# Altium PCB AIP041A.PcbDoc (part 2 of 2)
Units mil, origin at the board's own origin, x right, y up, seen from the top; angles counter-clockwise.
Board outline 2650 x 1600 mil, 2 copper layers (Top Layer, Bottom Layer), stack 62 mil thick; 99 components, 51 nets, 275 pads, 83 vias.
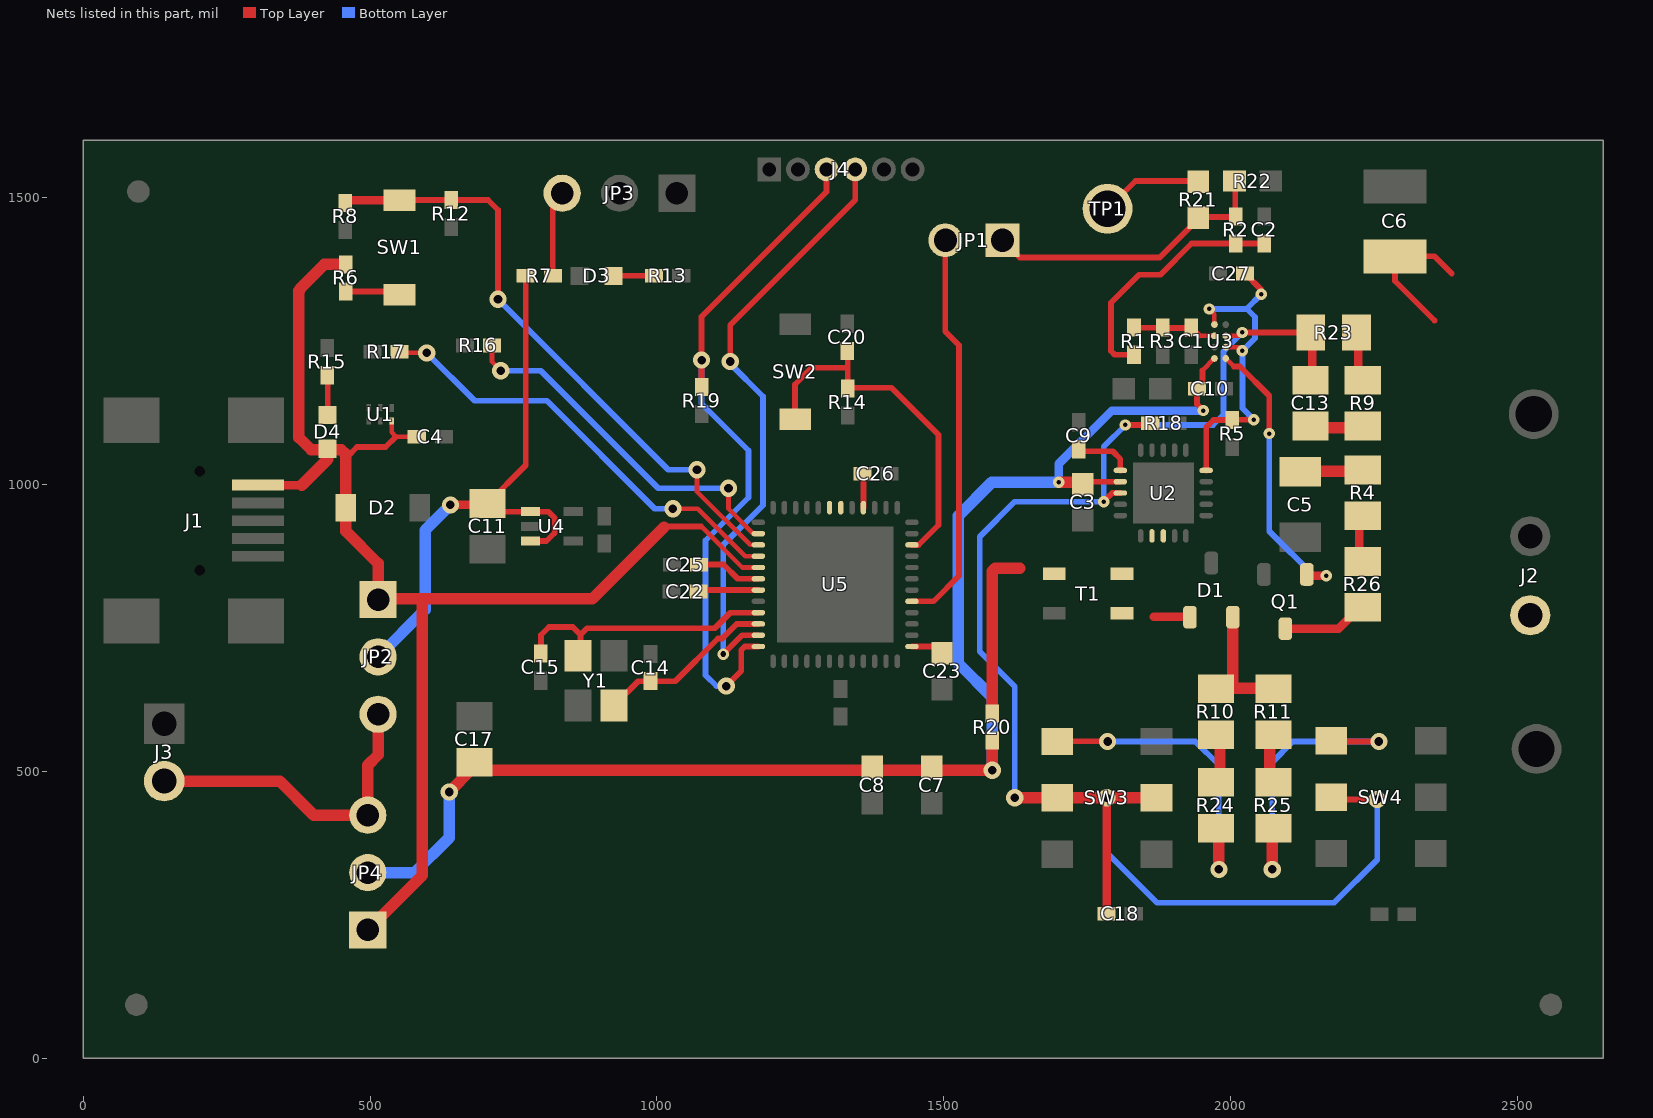
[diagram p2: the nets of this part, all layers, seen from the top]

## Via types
v1: diameter 30, hole 15, Top Layer to Bottom Layer, tented both sides, 48 vias
v2: diameter 19.68, hole 7.87, Top Layer to Bottom Layer, tented both sides, 17 vias
v3: diameter 19.68, hole 7.87, Top Layer to Bottom Layer, tented bottom, 17 vias
v4: diameter 20, hole 10, Top Layer to Bottom Layer, tented both sides, 1 vias

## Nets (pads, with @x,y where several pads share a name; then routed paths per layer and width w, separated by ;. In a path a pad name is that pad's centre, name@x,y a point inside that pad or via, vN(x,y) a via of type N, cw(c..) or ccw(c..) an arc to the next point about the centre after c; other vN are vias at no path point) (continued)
HV: C5.1 C6.1 C13.1 D1.2 J2.1 R4.2 R9.2 R10.2 R11.2 | length 653.9
  Top Layer w10: 2356,1286 2287,1355 C6.1@2287,1397.98 2356.02,1397.98 2386,1368
  Top Layer w20: R10.2@1968,645 R11.2@2056,645 ; R10.2@2004.4,647.31 D1.2@2004.4,771.76 ; C5.1@2113,1023.09 R4.2@2223.09,1023.09 ; C13.1@2140.57,1099 R9.2@2220,1099
NetC1_2: C1.2 R1.2 R3.2 U3.C2 | length 145.5
  Top Layer w8: 1945.9,1259.34 U3.C2@1972.28,1259.34
  Top Layer w10: R1.2@1832,1273.62 R3.2@1881.62,1273.62 ; R3.2@1882.12,1273.12 1932.12,1273.12 1945.9,1259.34
NetC2_1: C2.1 R1.1 R2.2 | length 437.1
  Top Layer w10: R1.1@1832,1226.38 1798.62,1226.38 1792,1233 1792,1317 1841,1366 1878,1366 1932.39,1420.39 R2.2@2009.49,1420.39 C2.1@2059.49,1420.39
NetC9_1: C9.1 U2.1 | length 97.9
  Top Layer w10: C9.1@1736,1058 1795,1058 1808.28,1044.72 U2.1@1808.28,1024.64
NetC14_2: C14.2 U5.46 Y1.1 | length 310.8
  Top Layer w10: Y1.1@925.31,614.7 967.51,656.9 988,656.9 1032,656.9 1106.62,731.52 1114,731.52 1139.46,756.98 U5.46@1177.13,756.98
NetC15_2: C15.2 U5.45 Y1.3 | length 462.4
  Top Layer w10: C15.2@798,705.15 798,737.52 812,751.52 853.49,751.52 867,738.01 ; Y1.3@867,714.52 867,738.01 ; U5.45@1177.13,776.67 1128,776.67 1100.86,749.52 878.51,749.52 867,738.01
NetC22_1: C22.1 U5.43 | length 106.1
  Top Layer w10: C22.1@1071.03,816.04 U5.43@1177.13,816.04
NetC23_1: C23.1 U5.13 | length 40.9
  Top Layer w10: U5.13@1444.85,717.61 C23.1@1485.75,717.61
NetC25_1: C25.1 U5.42 | length 113.8
  Top Layer w10: C25.1@1073.62,860.52 1116.48,860.52 1141.28,835.72 U5.42@1177.13,835.72
NetC26_2: C26.2 U5.28 | length 50.1
  Top Layer w10: U5.28@1360.2,959.74 C26.2@1360.2,1009.86
NetD1_1: D1.1 T1.2 | length 62.7
  Top Layer w15: 1866.88,769.76 D1.1@1929.6,769.76
NetD3_2: D3.2 R13.2 | length 66.9
  Top Layer w10: D3.2@924.53,1364 R13.2@991.38,1364
NetD4_2: D4.2 R15.2 | length 68.1
  Top Layer w10: D4.2@426,1121.56 R15.2@426,1189.62
NetJP1_1: JP1.1 R2.1 R21.1 R22.2 | length 508.2
  Top Layer w10: JP1.1@1603,1426 1632.99,1396 1877,1396 R21.1@1944,1463 ; R21.1@1944,1466.5 2008.36,1466.5 R22.2@2008.36,1529.14
NetJP3_3: JP3.3 R7.1 | length 150.8
  Top Layer w10: R7.1@818.62,1364 818.62,1491.62 JP3.3@835,1508
NetQ1_3: Q1.3 R26.1 | length 145.4
  Top Layer w15: Q1.3@2096,748.76 2188.76,748.76 R26.1@2226,786
NetR4_1: R4.1 R26.2 | length 78
  Top Layer w15: R26.2@2225,867 R4.1@2225,945
NetR6_1: R6.1 SW1.2 | length 87.9
  Top Layer w10: R6.1@457.37,1336.75 SW1.2@545.31,1336.75
NetR9_1: R9.1 R23.2 | length 82
  Top Layer w15: R9.1@2223,1183 R23.2@2223,1265
NetR10_1: R10.1 R24.2 | length 82
  Top Layer w20: R24.2@1982,481 R10.1@1982,563
NetR11_1: R11.1 R25.2 | length 79
  Top Layer w20: R25.2@2069,485 R11.1@2069,564
NetR16_1: R16.1 U5.38 | length 638.1
  Top Layer w8: R16.1@712.62,1242.52 712.62,1213.9 v1(728,1198.52) ; v1(1125,993.52) 1125,957.76 1168.3,914.46 U5.38@1177.13,914.46
  Bottom Layer w10: v1(728,1198.52) 797.48,1198.52 1002.48,993.52 v1(1125,993.52)
NetR17_1: R17.1 U5.40 | length 770.3
  Top Layer w8: R17.1@553.62,1229.52 v1(599,1229.52) ; v1(1028,958) 1071.52,958 1154.43,875.09 U5.40@1177.13,875.09
  Bottom Layer w10: v1(599,1229.52) 682.52,1146 808.52,1146 996.52,958 v1(1028,958)
NetR20_1: R20.1 T1.4 | length 298.4
  Top Layer w20: R20.1@1585,600.62 1585,849 1590,854 1633,854
NetR21_2: R21.2 TP1.1 | length 178.1
  Top Layer w10: TP1.1@1786,1481 1834.5,1529.5 R21.2@1944,1529.5
NetT1_1: T1.1 U2.7 U2.8
PUR: R8.1 R12.2 SW1.1 U5.39 | length 1083.1
  Top Layer w8: v1(1070,1026) 1070,987.52 1162.75,894.78 U5.39@1177.13,894.78
  Top Layer w10: SW1.1@551.37,1496.05 R12.2@641.52,1496.13 705.87,1496.13 723,1479 v1(723,1323)
  Top Layer w15: R8.1@457,1496.05 SW1.1@551.37,1496.05
  Bottom Layer w10: v1(723,1323) 1020,1026 v1(1070,1026)
PWM+_MSP: JP1.2 U5.17 | length 695.6
  Top Layer w10: U5.17@1444.85,796.35 1482.35,796.35 1527,841 1527,1243 1503,1267 JP1.2@1503,1426
REXT: C27.1 R5.1 U2.15 U3.B1 U3.D2 | length 592.2
  Top Layer w8: v2(1963.03,1306.18) 1972.28,1296.93 U3.D2@1972.28,1279.03 ; U3.B1@1991.96,1239.66 2014.55,1239.66 v2(2021.03,1233.18)
  Top Layer w10: U2.15@1957.89,1024.64 1957.89,1099.89 1970.62,1112.62 R5.1@2003,1112.62 ; R5.1@2003.38,1113 v2(2041,1113) ; C27.1@2025.62,1368 2054,1339.62 v2(2054,1332)
  Bottom Layer w10: v2(1963.03,1306.18) 2028.82,1306.18 ; v2(2041,1113) 2021.03,1132.97 v2(2021.03,1233.18) 2043,1255.15 2043,1292 2028.82,1306.18 ; v2(2054,1332) 2028.82,1306.82 2028.82,1306.18
RNET1: R24.1 SW3.1 | length 550.7
  Top Layer w10: SW3.1@1697.97,552.31 v1@1785.69,552.31
  Top Layer w20: v1(1980,329) R24.1@1980,399
  Bottom Layer w10: v1(1786,552) 1939,552 1980,511 v1(1980,329)
RNET2: R25.1 SW4.1 | length 541.6
  Top Layer w10: SW4.1@2177.28,552 v1(2259,552)
  Top Layer w20: v1(2073,329) R25.1@2073,401
  Bottom Layer w10: v1(2073,329) 2073,516 2109,552 v1(2259,552)
SBWTCK: J4.4 U5.47 | length 1060.5
  Top Layer w10: v4(1116,704.52) 1148.77,737.3 U5.47@1177.13,737.3 ; v1(1128,1214.52) 1128,1278 1346,1496 J4.4@1346,1551.49
  Bottom Layer w10: v4(1116,704.52) 1116,895 1185,964 1185,1153.81 v1@1128,1210.82
SBWTDIO: J4.3 R19.1 U5.48 | length 1234.2
  Top Layer w10: R19.1@1078,1170.15 v1(1078,1217) 1078,1292.52 1296,1510.52 J4.3@1296,1549.52 ; v1(1121,648.57) 1147.29,674.87 1147.29,711.52 1153.38,717.61 U5.48@1177.13,717.61
  Bottom Layer w10: v1(1078,1217) 1078,1141.52 1160,1059.52 1160,977.52 1085,902.52 1085,667.52 1103.95,648.57 v1(1121,648.57)
SCL: U5.31
SDA: U5.30
TRIG: C20.1 R14.1 SW2.2 U5.22 | length 640.1
  Top Layer w10: SW2.2@1241.05,1114.17 1241.05,1174.57 1270,1203.52 1333.05,1203.52 ; R14.1@1333.05,1167.47 C20.1@1333.05,1233.22 ; R14.1@1333.05,1169 1409,1169 1491,1087 1491,929.52 1456.25,894.78 U5.22@1444.85,894.78
VBUS: C4.1 D2.1 D4.1 J1.1 JP2.1 JP4.1 R6.2 U1.6 U5.41 | length 2416.7
  Top Layer w8: U1.6@537.48,1110.92 537.48,1091.04 545,1083.52 C4.1@581.38,1083.52 ; 1077.52,927 1149.12,855.41 U5.41@1177.13,855.41
  Top Layer w10: D4.1@426,1061 D4.1@426,1062.5 ; 461.03,1049.49 477.06,1065.52 527,1065.52 545,1083.52 ; 1011,927 1077.52,927
  Top Layer w15: J1.1@304.5,999 381,999
  Top Layer w20: 381,999 426,1044 D4.1@426,1061 ; R6.2@457.37,1384 420.48,1384 377,1340.52 377,1339 376,1338 376,1082 397,1061 D4.1@426,1061 ; D2.1@457.53,956.52 D2.1@457.53,959.52 ; JP4.1@496,223.52 591,318.52 591,800.52 ; JP2.1@514,799.52 514,862.52 457.53,918.99 D2.1@457.53,959.52 ; JP2.1@514,800.52 887.52,800.52 1012.5,925.5 ; D4.1@426,1061 449.53,1061 457.53,1052.99 D2.1@457.53,959.52
VDIV: C13.2 C18.1 R18.2 R23.1 SW3.2 SW3.5 SW4.2 U2.3 U3.C1 | length 2777.6
  Top Layer w8: U3.C1@1991.96,1259.34 2015.19,1259.34 v2(2021.03,1265.18)
  Top Layer w10: v2(1779.08,970.27) 1794.08,985.27 U2.3@1808.28,985.27 ; v2(1817,1104) R18.2@1857.38,1104 ; v2(2021.03,1265.18) R23.1@2143,1265.18 ; SW4.2@2179.86,451 v1(2256,451)
  Top Layer w15: C18.1@1784.59,252 v1(1784.59,453.88) ; C13.2@2143,1187.43 R23.1@2143,1265
  Top Layer w20: v1(1624,453.88) SW3.2@1697.97,453.88 SW3.5@1871.2,453.88
  Bottom Layer w10: v1(1624,453.88) 1624,648 1563,709 1563,909 1624.27,970.27 v2(1779.08,970.27) 1779.08,1066.08 v2(1817,1104) 1970,1104 1987.97,1121.97 1987.97,1232.12 v2(2021.03,1265.18) ; v1(1784.59,453.88) 1784.59,358.68 1872.27,271 2181,271 2256,346 v1(2256,451)
VDRV: C3.1 C7.1 C8.1 C10.1 C17.1 JP4.2 R20.2 U2.2 U3.A2 | length 2457.5
  Top Layer w8: 1951.62,1199.31 U3.A2@1972.28,1219.97
  Top Layer w10: C3.1@1743,1004.95 U2.2@1808.28,1004.95 ; C10.1@1941.76,1167 1941.76,1140.24 v2(1953,1129) ; C10.1@1951.62,1167 1951.62,1199.31
  Top Layer w20: v1(638,464) C17.1@677,503 ; C17.1@677,502 v1(1585,502) R20.2@1585,552 ; v2(1701,1004) C3.1@1739.5,1004
  Bottom Layer w15: v2@1701,1004.95 1701,1036.34 1793.66,1129 v2(1953,1129)
  Bottom Layer w20: JP4.2@496,323.52 577.52,323.52 638,384 v1(638,464) ; v1(1585,502) 1585,629 1525.83,688.17 1525.83,945.83 1584,1004 v2(1701,1004)
VGATE: Q1.1 U3.A1 | length 501.8
  Top Layer w8: U3.A1@1991.96,1219.97 2005.94,1206
  Top Layer w10: 2005.94,1206 2017,1206 2068,1155 v2(2068,1089)
  Top Layer w15: Q1.1@2135.65,841 v2(2167,841)
  Bottom Layer w10: v2(2068,1089) 2068,918.74 2145.74,841 v2(2167,841)
VIN: J3.2 JP2.3 JP4.3 | length 563.1
  Top Layer w20: J3.2@141,483 342.53,483 402,423.53 JP4.3@496,423.52 ; JP4.3@496,423.52 496,510.52 514,528.52 JP2.3@514,599.52
VREST: C11.1 JP2.2 R7.2 U4.1 U4.3 | length 1000
  Top Layer w10: C11.1@704.41,952.74 U4.1@779.6,952.74 811.09,952.74 822,941.83 822,915.66 ; C11.1@705,967.15 771.38,1033.52 R7.2@771.38,1364 ; U4.3@779.6,901.55 807.41,901.55 821.52,915.66
  Top Layer w15: v1(640,964.52) C11.1@702.38,964.52
  Bottom Layer w20: JP2.2@514,699.52 596,781.52 596,920.52 v1(640,964.52)
pads on no net: D1.3 FID1.1 FID2.1 FID3.1 H1.0 H2.0 H3.0 H4.0 J1.4 J1.MH1 J1.MH2 J4.1 J4.2 J4.6 SH-JP1.0 SH-JP2.0 SH-JP3.0 SH-JP4.0 SW3.3 SW3.4 SW4.3 SW4.4 U1.4 U1.5 U2.9 U2.10 U2.11 U2.12 U2.13 U2.14 U2.16 U2.17 U4.4 U5.2 U5.3 U5.4 U5.5 U5.6 U5.8 U5.9 U5.14 U5.15 U5.16 U5.18 U5.19 U5.20 U5.21 U5.23 U5.24 U5.25 U5.26 U5.29 U5.32 U5.33 U5.34 U5.35 U5.36

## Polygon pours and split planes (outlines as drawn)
GND on Bottom Layer "Bottom Layer-No Net" (solid, remove dead copper, pour order 11): 22,1572 2608,1572 2608,42 2611,39 28,39 25,42
HV on Top Layer "Top Layer-No Net" (solid, remove dead copper, pour order 8): 1995,641 1995,706.91 1997.99,709.91 2283.18,709.91 2346.96,773.83 2346.96,962.42 2325.87,983.56 2231.88,983.56 2201.91,1013.59 2201.91,1086.43 2232.19,1116.78 2293.37,1116.78 2343.81,1167.33 2343.81,1293.17 2259.1,1378.06 2259.1,1416.01 2266.07,1423 2337.64,1423 2403.34,1357.17 2403.34,867.26 2474,796.45 2578.36,796.45 2581,793.8 2581,699.92 2521.2,640 2520.21,641 1996,641

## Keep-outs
Keep-Out Layer:
  lines w10: -5,0 -5,1605 2650,1605 2655,1600 2655,0 ; 0,-5 2650,-5 ; -6,78 ccw(c-1,78) -1,73 ; -6,78 ccw(c-1,78) -1,73 ; -6,78 ccw(c-1,78) -1,73 ; -6,78 ccw(c-1,78) -1,73 ; -6,78 ccw(c-1,78) -1,73 ; -6,78 ccw(c-1,78) -1,73
  text ".Layer_Name" at 577,-858.49 h60

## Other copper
Top Layer:
  rectangle net GND: 262.88,766 342,875.3
  rectangle net NetT1_1: 1865.4,851.47 1883.08,910.47
  rectangle net GND: 51.02,1088.48 337,1135
  rectangle net GND: 48,743 330,783
  rectangle net GND: 118,589.52 163,756
  region net VBUS: 588.1,772.89 605,790.52 586.43,808.32 569.53,790.68
  rectangle net NetD1_1: 1802.26,691 1896,783
  rectangle net GND: 1613,692 1688,782.37
  rectangle net NetT1_1: 1810,851.47 1883.08,868
  rectangle net NetR20_1: 1613,834 1693,888.37
  rectangle net NetT1_1: 1802.26,834 1896,889
  text ".Layer_Name" at 577,-858.49 h60
Bottom Layer:
  pour cut-out: 1747,526 1773,500 1865,500 1903,462 1903,318 1963,258 2109,258 2162,311 2162,446 2206,490 2301,490 2345,534 2345,616 2340,621 1747.21,621 1747,621.21
  pour cut-out: 2617,629 2419,629 2419,863 2428,880 2608,880.97 2618,867
  pour cut-out: 1735.3,904 1885.06,904 1901.06,888 1901.06,719.08 1892.97,711 1641.33,711 1641,722 1641.33,808.01
  text ".Layer_Name" at 577,-858.49 h60

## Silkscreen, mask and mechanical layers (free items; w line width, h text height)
Top Overlay:
  lines w10: 1701,742 1794,742 ; 1703,902 1703,1313 1704,1314 2282,1314 2282,741.21 2117,741.21 ; 1911,741 2073.5,741
  text "SBW" at 1293,1495 h20
  text "PU" at 813,1426 h20
  text "EN" at 912,1426 h20
  text "MSP" at 1016,1426 h20
  text "MSP" at 1476,1340 h20
  text "PWM" at 1579,1340 h20
  text "14.5 x 14.5 mm" at 2295,1159.58 h25 r270
  text "DRV2700" at 2332,1156 h25 r270
  text "GND" at 2483,1002 h28
  text "-" at 2363,895 h20 r90
  text "USB" at 600,772.89 h20 r90
  text "+" at 2362,764 h20 r90
  text "MSP" at 600,671.52 h20 r90
  text "." at 1166,661.52 h20
  text "HIGH VOLTAGE" at 2289,645 h30
  text "-" at 306,596 h20 r90
  text "Power Routing" at 448,575.52 h20 r90
  text "VIN" at 600,571.52 h20 r90
  text "+" at 305,465 h20 r90
  text "VIN" at 580,404.52 h20 r90
  text "Ext VIN" at 69,365.47 h20
  text "5.5VDC MAX" at 37,330 h20
  text "DRV" at 580,295.52 h20 r90
  text "DRV2700" at 818,283 h50
  text "EVM-HV500" at 1172,283 h50
  text "Up/Up : 158V" at 1952.31,252 h20
  text "Up/Down : 212V" at 1912.32,213.22 h20
  text "Power Routing" at 430,197.52 h20 r90
  text "USB" at 580,196.52 h20 r90
  text "Down/Up : 275V" at 1908.99,174.44 h20
  text "Down/Down : 500V" at 1869,138 h20
  text "AIP041A" at 2139,39 h30
  text ".Layer_Name" at 577,-858.49 h60
Bottom Overlay:
  text ".Layer_Name" at 577,-858.49 h60
Top Paste:
  text ".Layer_Name" at 577,-858.49 h60
Bottom Paste:
  text ".Layer_Name" at 577,-858.49 h60
Top Solder:
  text ".Layer_Name" at 577,-858.49 h60
  text ".Layer_Name" at 577,-858.49 h60
Bottom Solder:
  text ".Layer_Name" at 577,-858.49 h60
Drill Guide:
  text ".Layer_Name" at 577,-858.49 h60
M1 Board Outline:
  lines w10: 0,0 0,1600 ; 0,0 2650,0 2650,1600 0,1600 ; 0,0 0,1600
  text ".Layer_Name" at 577,-858.49 h60
M2 Board Dimensions:
  rectangle: 125,-410.5 500,-285.5
  rectangle: 0,-285.5 125,-160.5
  lines w7: 0,-285.5 1000,-285.5 ; 125,-410.5 125,-160.5 ; 250,-410.5 250,-160.5 ; 500,-410.5 500,-160.5 ; 750,-410.5 750,-160.5 ; 0,-410.5 0,-160.5 1000,-160.5 1000,-410.5 0,-410.5
  text ".Layer_Name" at 577,-858.49 h60
M3 3D STEP Top:
  text ".Layer_Name" at 577,-858.49 h60
M4 3D STEP Bottom:
  text ".Layer_Name" at 577,-858.49 h60
M5 Assembly Top:
  lines w10: -292,-930.17 6308,-930.17 ; -292,-726.83 6310,-726.83 ; -292,-523.5 -292,-1133.5 3713,-1133.5 6310,-1133.5 6310,-523.5 -291.5,-523.5 -291.5,-1133.5 1284,-1133.5 ; 2173,-1133.5 2173,-523.5 ; 3440,-726.83 3440,-523.5 ; 4280,-726.83 4280,-523.5 ; 4902,-1140 4902,-937.17
  text "COMPONENTS MARKED 'DNP' SHOULD NOT BE POPULATED." at 1153.5,-318.5 h60
  text "ASSEMBLY VARIANT:" at 1153,-434 h60
  text ".VariantName" at 2189,-434 h60
  text "PCB VIEWED FROM TOP SIDE" at -228.5,-655.67 h60
  text "BOARD #:" at 2248,-655.67 h60
  text ".PRJ_Number" at 2793.5,-655.67 h60
  text "REV:" at 3638,-655.67 h60
  text ".PCB_Rev" at 3929.5,-655.67 h60
  text "SVN REV:" at 4476,-655.67 h60
  text ".VersionControl_RevNumber" at 4982,-655.67 h60
  text "IGNORE ->" at -228.5,-858.49 h60
  text "PLOT NAME =" at -228.5,-1064.34 h60
  text ".plot_File_Name" at 577,-1064.34 h60
  text "GENERATED    :" at 2250,-1064.34 h60
  text ".Print_Date" at 3119.5,-1064.34 h60
  text ".Print_Time" at 3848.5,-1064.34 h60
  text "TEXAS INSTRUMENTS" at 5113,-1064.34 h60
M6 Assembly Bottom:
  lines w10: -292.5,-727.33 6309.5,-727.33 ; -290.5,-930.67 6309.5,-930.67 ; 1115.5,-1140.5 1115.5,-937.67 ; 1737.5,-727.33 1737.5,-524 ; 2577.5,-727.33 2577.5,-524 ; 3844.5,-1134 3844.5,-524 ; 4733.5,-1134 6309,-1134 6309,-524 -292.5,-524 -292.5,-1134 2304.5,-1134 6309.5,-1134 6309.5,-524
  text "COMPONENTS MARKED 'DNP' SHOULD NOT BE POPULATED." at 6102,-318 h60
  text ".VariantName" at 5058,-434 h60
  text "ASSEMBLY VARIANT:" at 6097,-434 h60
  text ".VersionControl_RevNumber" at 1035.5,-656.17 h60
  text "SVN REV:" at 1541.5,-656.17 h60
  text ".PCB_Rev" at 2088,-656.17 h60
  text "REV:" at 2379.5,-656.17 h60
  text ".PRJ_Number" at 3224,-656.17 h60
  text "BOARD #:" at 3769.5,-656.17 h60
  text "PCB VIEWED FROM BOTTOM SIDE" at 6246,-656.17 h60
  text "IGNORE ->" at 2547.85,-858.49 h60
  text "TEXAS INSTRUMENTS" at 904.5,-1064.84 h60
  text ".Print_Time" at 2169,-1064.84 h60
  text ".Print_Date" at 2898,-1064.84 h60
  text "GENERATED    :" at 3767.5,-1064.84 h60
  text ".plot_File_Name" at 5440.5,-1064.84 h60
  text "PLOT NAME =" at 6246,-1064.84 h60
M9 Title Sheet:
  drawing of 56 lines, arcs and shapes, not listed
  text "1" at 739.84,8036.5 h70
  text "2" at 3235.5,8036.5 h70
  text "3" at 5724.84,8036.5 h70
  text "4" at 8231.51,8036.5 h70
  text "5" at 10730.5,8036.5 h70
  text "A" at -416.5,6893.5 h70
  text "B" at -416.5,4513.5 h70
  text "B" at 14383.5,4513.5 h70
  text "C" at -416.5,2138.5 h70
  text "C" at 14383.5,2138.5 h70
  text "PROJECT TITLE:" at 11343.5,277.5 h45
  text ".PRJ_Title" at 11393.5,144.17 h70
  text "DESIGNED FOR:" at 11343.5,-23.5 h45
  text ".PRJ_Customer" at 11393.5,-163.5 h70
  text "D" at -416.5,-231.5 h70
  text "D" at 14383.5,-231.5 h70
  text "FILE NAME:" at 11343.5,-323.5 h45
  text ".PCB_File_Name_No_Path" at 11393.5,-443.5 h70
  text "Texas Instruments (TI) and/or its licensors do not warrant the accuracy or completeness of this specification" at 6374,-605.34 h45
  text "ENGINEER:" at 11343.5,-613.5 h45
  text "LAYOUT BY:" at 12848.5,-613.5 h45
  text "or any information contained therein. TI and/or its licensors do not warrant that this design will meet" at 6329.01,-718 h45
  text ".PRJ_Engineer" at 11393.5,-768.49 h70
  text ".PCB_Layout" at 12899,-768.49 h70
  text "the specifications, will be suitable for your application or fit for any particular purpose, or will operate in" at 6329.01,-830.67 h45
  text ".Layer_Name" at 577,-858.49 h60
  text "ALTIUM DESIGNER VERSION:" at 12848.5,-923.5 h45
  text "an implementation. TI and/or its licensors do not warrant that the design is production worthy. You should" at 6329.01,-943.33 h45
  text "completely validate and test your design implementation to confirm the system functionality for your application." at 6374,-1056 h45
  text ".print_Scale" at 11393.5,-1056.83 h70
  text ".Application_BuildNumber" at 12899,-1056.83 h70
  text "1" at 739.84,-1263.5 h70
  text "2" at 3235.5,-1263.5 h70
  text "3" at 5724.84,-1263.5 h70
  text "4" at 8231.51,-1263.5 h70
  text "5" at 10730.5,-1263.5 h70
  text "6" at 13235.5,-1263.5 h70
M10 Fab Notes:
  drawing of 185 lines, arcs and shapes, not listed
  text "DESIGN INFORMATION" at 12381.02,5910 h60
  text "MIN. TRACK WIDTH:" at 11736.46,5730 h60
  text "8" at 12832.7,5730 h60
  text "MIL" at 12987.46,5730 h60
  text "MIN. CLEARANCE:" at 11736.46,5598 h60
  text "0.2" at 12772.7,5598 h60
  text "mm" at 12987.46,5598 h60
  text "MIN. VIA PAD SIZE:" at 11736.46,5466 h60
  text "24" at 12802.71,5466 h60
  text "MIL" at 12987.46,5466 h60
  text "0.05mm (2MIL)" at 12431.46,5324.29 h60
  text "MINIMUM ANNULAR RING" at 11407.23,5320 h60
  text "EXTERNAL" at 13139.46,5320 h60
  text "PER" at 11607.23,5202 h60
  text "IPC-D-275 CLASS 2 LEVEL C" at 11827.23,5202 h60
  text "MIL, HOLES" at 13315.46,5089.71 h60
  text "+/-" at 12923,5089 h60
  text "+/-" at 13777,5089 h60
  text "REGISTRATION TOLERANCES:" at 11407.23,5084 h60
  text "METAL" at 12607,5084 h60
  text "5" at 13183.2,5084 h60
  text "3" at 14016.2,5084 h60
  text "MIL" at 14132.46,5084 h60
  text "MATERIAL:" at 11332.46,4874.54 h60
  text "FR-4 High Tg" at 12318.9,4734.21 h60
  text "FR-408" at 11753.46,4725.64 h60
  text "X" at 12165.46,4725.64 h60
  text "OTHER" at 13241.46,4725.64 h60
  text "62 MIL (1.6mm) +/-10%" at 12073.56,4562.92 h60
  text "THICKNESS:" at 11407.23,4558.64 h60
  text "X" at 11945.4,4558.64 h60
  text "OTHER" at 13358.46,4558.64 h60
  text "TOLERANCE:" at 11407.23,4400.64 h60
  text "X" at 12246.53,4400.64 h60
  text "ANSI IPC-6012 TYPE 3 CLASS 2" at 12433.48,4400.64 h60
  text "OTHER +/-" at 12433.46,4244.64 h60
  text "BOW & TWIST:" at 11407.23,4087.64 h60
  text "X" at 12246.53,4087.64 h60
  text "ANSI IPC-6012 TYPE 3 CLASS 2" at 12433.48,4087.64 h60
  text "OTHER +/-" at 12433.46,3929.13 h60
  text "DRILLING:" at 11332.46,3790.64 h60
  text "REFERENCE:" at 11407.23,3673.64 h60
  text "X" at 12055.46,3673.64 h60
  text "AS SHOWN" at 12242.46,3673.64 h60
  text "X" at 12956.46,3673.64 h60
  text "NC_DRILL FILES" at 13093.46,3673.64 h60
  text "PTH MIN COPPER THICKNESS:" at 11407.23,3515.64 h60
  text "X" at 12757.46,3515.64 h60
  text "1MIL" at 12894.46,3515.64 h60
  text "OTHER" at 13391.46,3515.64 h60
  text "BOARD FINISH:" at 11332.46,3356.64 h60
  text "SILKSCREEN:" at 11487.68,3238.64 h60
  text "X" at 12436.46,3238.64 h60
  text "TOP" at 12562.46,3238.64 h60
  text "BOTTOM" at 13073.46,3238.64 h60
  text "SILKSCREEN COLOR:" at 11487.68,3071.64 h60
  text "X" at 12435.42,3071.64 h60
  text "WHITE" at 12562.46,3071.64 h60
  text "OTHER" at 13073.46,3071.64 h60
  text "SOLDER RESIST COLOR:" at 11487.68,2901.64 h60
  text "X" at 12055.42,2742.44 h60
  text "GREEN" at 12182.46,2742.44 h60
  text "BLUE" at 12773.46,2742.44 h60
  text "OTHER" at 13311.46,2742.44 h60
  text "IMMERSION GOLD (ENIG)" at 12393.46,2553.92 h60
  text "ENEPIG" at 13731,2550.64 h60
  text "SURFACE FINISH:" at 11332.46,2549.64 h60
  text "X" at 12206.51,2549.64 h60
  text "IMM. TIN/SILVER OR EQUIV" at 11662,2392.64 h60
  text "OTHER" at 13093.46,2392.64 h60
  text "ARRAY/PANEL:" at 11332.46,2213.64 h60
  text "CUT AND TRIM PER MECH LAYER 1" at 12393.46,2209.35 h60
  text "N.C. ROUTE" at 12393.46,2057.64 h60
  text "X" at 13072.46,2057.64 h60
  text "V. SCORE" at 13259.46,2057.64 h60
  text "CERTIFICATION:" at 11332.46,1920.64 h60
  text "MATERIALS AND WORKMANSHIP FOR ALL PCBS" at 12057.46,1920.64 h60
  text "TO MEET OR EXCEED THE REQUIREMENTS OF:" at 12057.46,1822.64 h60
  text "X" at 11683.96,1686.13 h60
  text "ANSI IPC-A-600F CLASS ->" at 11822.96,1686.13 h60
  text "X" at 13462.02,1686.13 h60
  text "2" at 13580.96,1686.14 h60
  text "1" at 13265.96,1684.64 h60
  text "3" at 13934.96,1684.64 h60
  text "X" at 11686.02,1526.64 h60
  text "UL 94V-0" at 11822.96,1526.64 h60
  text "X" at 12498.02,1526.64 h60
  text "RoHS" at 12634.96,1526.64 h60
  text "OTHER" at 13279.36,1526.64 h60
  text "PER ORDER" at 13676.42,1526.64 h60
  text "ADDITIONAL REQUIREMENTS:" at 11332.46,1385.64 h60
  text "MICROSECTION:" at 11407.23,1270.64 h60
  text "YES" at 12312.96,1270.64 h60
  text "REQUIRED" at 13174.46,1114.49 h60
  text "BARE BOARD ELEC. TEST:" at 11407.23,1111.64 h60
  text "NONE" at 12712.96,1111.64 h60
  text "X" at 13047.46,1111.64 h60
  text "PER ORDER" at 13766.46,1111.64 h60
  text "MANUFACTURER'S UL:" at 11407.23,954.64 h60
  text "RAIL" at 12572.96,950.35 h60
  text "METAL" at 13064.77,950.35 h60
  text "X" at 13440,950 h60
  text "SILK" at 13576.46,950.35 h60
  text ".Layer_Name" at 577,-858.49 h60
M11 Gerber Information:
  lines w10: -292,-930.17 6308,-930.17 ; -292,-726.83 6310,-726.83 ; -292,-523.5 -292,-1133.5 3713,-1133.5 6310,-1133.5 6310,-523.5 -291.5,-523.5 -291.5,-1133.5 1284,-1133.5 ; 2173,-1133.5 2173,-523.5 ; 3440,-726.83 3440,-523.5 ; 4280,-726.83 4280,-523.5 ; 4902,-1140 4902,-937.17
  text "ALL ARTWORK VIEWED FROM TOP SIDE" at -228.5,-655.67 h60
  text "BOARD #:" at 2248,-655.67 h60
  text ".PRJ_Number" at 2793.5,-655.67 h60
  text "REV:" at 3638,-655.67 h60
  text ".PCB_Rev" at 3929.5,-655.67 h60
  text "SVN REV:" at 4476,-655.67 h60
  text ".VersionControl_RevNumber" at 4982,-655.67 h60
  text "LAYER NAME =" at -228.5,-858.49 h60
  text "PLOT NAME =" at -228.5,-1064.34 h60
  text ".plot_File_Name" at 577,-1064.34 h60
  text "GENERATED    :" at 2250,-1064.34 h60
  text ".Print_Date" at 3119.5,-1064.34 h60
  text ".Print_Time" at 3848.5,-1064.34 h60
  text "TEXAS INSTRUMENTS" at 5113,-1064.34 h60
M12 Stackup:
  lines w9: 11367,7282.17 14219,7282.17 ; 11367,7451.07 14219,7451.07 ; 11307,6186 ccw(c11362,6186) 11362,6131 14224,6131 ccw(c14224,6186) 14279,6186 14279,7796 ccw(c14224,7796) 14224,7851 11362,7851 ccw(c11362,7796) 11307,7796 11307,6186
  text "Layer Stack Up Detail for: AIP041A.PcbDoc" at 11367,7601.13 h68
  text "Layer" at 11367,7388.07 h39
  text "Gerber" at 12390.36,7388.07 h39
  text "Copper" at 12880.9,7388.07 h39
  text "Dielectric" at 13435.12,7388.07 h39
  text "Name" at 11367,7310.07 h39
  text "Document" at 12390.36,7310.07 h39
  text "Thickness" at 12880.9,7310.07 h39
  text "Material" at 13435.12,7310.07 h39
  text "Top Solder Mask" at 11367,7159.33 h55
  text "(.GTS)" at 12390.36,7159.33 h55
  text "Solder Resist" at 13435.12,7159.33 h55
  text "Top Layer" at 11367,6922.67 h55
  text "(.GTL)" at 12390.36,6922.67 h55
  text "1.4mil" at 12880.9,6922.67 h55
  text "FR-4" at 13435.12,6804.33 h55
  text "Bottom Layer" at 11367,6686 h55
  text "(.GBL)" at 12390.36,6686 h55
  text "1.4mil" at 12880.9,6686 h55
  text "Bottom Solder Mask" at 11367,6449.33 h55
  text "(.GBS)" at 12390.36,6449.33 h55
  text "Solder Resist" at 13435.12,6449.33 h55
  text ".Layer_Name" at 577,-858.49 h60
M13 Component Bodies Top:
  text ".Layer_Name" at 577,-858.49 h60
M14 Component Bodies Bottom:
  text ".Layer_Name" at 577,-858.49 h60
M15 Courtyards Top:
  text ".Layer_Name" at 577,-858.49 h60
M16 Courtyards Bottom:
  text ".Layer_Name" at 577,-858.49 h60
Drill Drawing:
  text "Drill Table" at 3945,1364 h60
  text ".legend" at 5122.5,725.5 h60
  text ".Layer_Name" at 577,-858.49 h60

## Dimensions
0,-410.5 to 1000,-410.5 on M2 Board Dimensions
0,0 to 2650,0 on M2 Board Dimensions
0,0 to 0,1600 on M2 Board Dimensions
